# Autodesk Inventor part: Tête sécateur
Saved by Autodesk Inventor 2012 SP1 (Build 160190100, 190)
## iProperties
Created: 2014-12
Part Number: Tête sécateur
Material: Default
Document SubType Name: Modeling
Designer: Bruno
Density: 1 g/cm^3
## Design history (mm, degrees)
node "Tête sécateur1"
node "Tête sécateur"
node "Base1"
